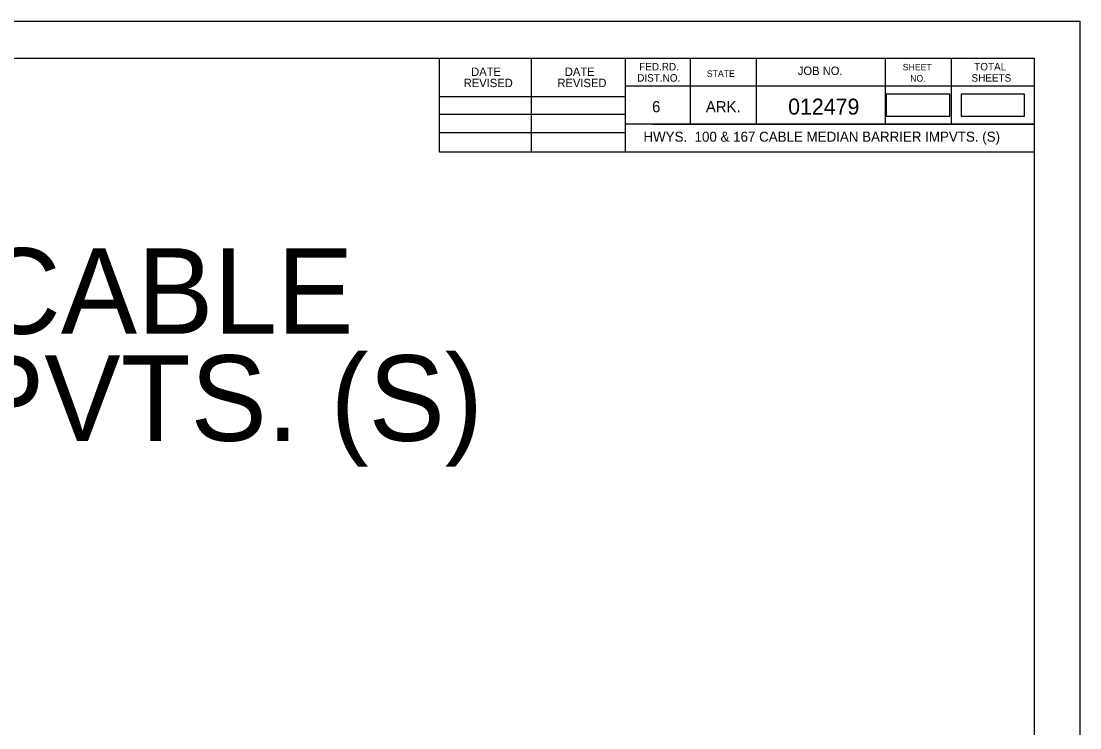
# Model space of a CAD drawing. Extents: x 1368042 to 1371376, y 380392 to 382637.
# Drawn here: x 1370261 to 1371376, y 381782 to 382525 of the extents above; entities that cross this region are included whole.
import ezdxf

# ---------------------------------------------------------------- set-up
doc = ezdxf.new("R2010")
doc.units = 0
for name, color, linetype in [('Default', 7, 'Continuous'), ('R_Border', 7, 'Continuous'), ('R_Border Notes', 7, 'Continuous'), ('R_No Plot', 7, 'Continuous')]:
    doc.layers.add(name, color=color, linetype=linetype)

msp = doc.modelspace()

# ---------------------------------------------------------------- linework, layer by layer
at = {"layer": 'Default'}
for points in [[(1371171.9, 382425.5), (1371238.8, 382425.5), (1371238.8, 382448.6), (1371171.9, 382448.6)], [(1371250.6, 382425.5), (1371317.5, 382425.5), (1371317.5, 382448.6), (1371250.6, 382448.6)]]:
    msp.add_lwpolyline(points, close=True, dxfattribs=at)
at = {"layer": 'R_Border'}
for p, q in [((1368166.2, 382486.4), (1371328, 382486.4)), ((1370701.6, 382387.6), (1370701.6, 382486.4)), ((1370798.4, 382387.6), (1370798.4, 382486.4)), ((1370897, 382486.4), (1370897, 382387.6)), ((1370965.4, 382486.4), (1370965.4, 382417)), ((1371034.8, 382486.4), (1371034.8, 382417)), ((1371170.6, 382486.4), (1371170.6, 382417)), ((1371240, 382486.4), (1371240, 382417)), ((1371328, 380431.8), (1371328, 382486.4)), ((1371328, 382457), (1370897, 382457)), ((1371328, 382457.2), (1371328, 382457.2)), ((1370701.6, 382446.2), (1370897, 382446.2)), ((1370701.6, 382427.6), (1370897, 382427.6)), ((1371328, 382417), (1370897, 382417)), ((1370926.6, 382417), (1371328, 382417)), ((1370701.6, 382408.2), (1370897, 382408.2)), ((1371328, 382387.6), (1370701.6, 382387.6))]:
    msp.add_line(p, q, dxfattribs=at)
at = {"layer": 'R_No Plot'}
msp.add_line((1368042.2, 382525.4), (1371375.6, 382525.4), dxfattribs=at)
msp.add_lwpolyline([(1368042.2, 382525.4), (1371375.6, 382525.4), (1371375.6, 380392), (1368042.2, 380392)], close=True, dxfattribs=at)

# ---------------------------------------------------------------- texts
at = {"layer": 'Default'}
for s, p in [('HWYS.  100 & 167 CABLE ', (1369171.8, 382196.5)), ('MEDIAN BARRIER IMPVTS. (S)  ', (1369000.9, 382083.9))]:
    msp.add_text(s, height=90.069, dxfattribs=at).set_placement(p)
at = {"layer": 'R_Border'}
for s, height, p in [('FED.RD.', 7.82, (1370911.8, 382473.6)), ('SHEET', 6.84, (1371189.2, 382473.6)), ('TOTAL', 7.82, (1371264.4, 382473.6)), ('DATE', 8.79, (1370735, 382467.8)), ('DATE', 8.79, (1370833.6, 382467.8)), ('DIST.NO.', 7.82, (1370909.8, 382461.8)), ('STATE', 6.84, (1370983, 382466.8)), ('JOB NO.', 8.79, (1371078.8, 382468.8)), ('NO.', 6.84, (1371197, 382461.8)), ('SHEETS', 7.82, (1371261.6, 382461.8)), ('REVISED', 8.79, (1370727.2, 382456)), ('REVISED', 8.79, (1370825.8, 382456)), ('6', 11.7, (1370925.4, 382429.6)), ('ARK.', 11.72, (1370982, 382429.6))]:
    msp.add_text(s, height=height, dxfattribs=at).set_placement(p)
at = {"layer": 'R_Border Notes'}
for s, height, p in [('012479', 16.8, (1371068.6, 382427.1)), ('HWYS.  100 & 167 CABLE MEDIAN BARRIER IMPVTS. (S)  ', 10.5, (1370916.3, 382398.6))]:
    msp.add_text(s, height=height, dxfattribs=at).set_placement(p)

doc.saveas('drawing.dxf')
